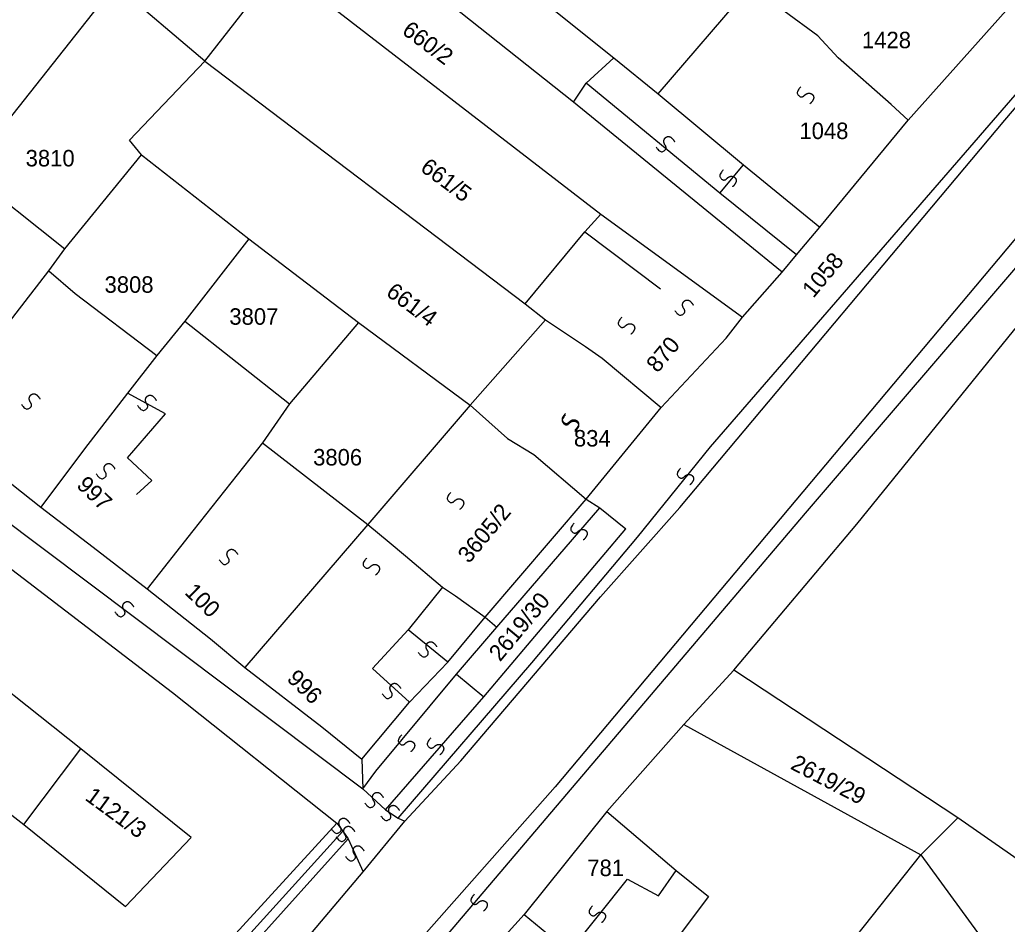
# Model space of a CAD drawing. Extents: x -581999 to -572728, y -1219553 to -1212032.
# Drawn here: x -577228 to -577108.1, y -1215298.5 to -1215188.7 of the extents above; entities that cross this region are included whole.
import ezdxf

# ---------------------------------------------------------------- set-up
doc = ezdxf.new("R2010")
doc.units = 0
for name, color, linetype in [('Vrstva 1', 7, 'Continuous'), ('Vrstva 2', 7, 'Continuous'), ('Vrstva 4', 7, 'Continuous'), ('Vrstva 6', 7, 'Continuous')]:
    doc.layers.add(name, color=color, linetype=linetype)

msp = doc.modelspace()

# ---------------------------------------------------------------- linework, layer by layer
at = {"layer": 'Vrstva 1'}
for p, q in [((-577108.375, -1215200.928), (-577078.069, -1215165.236)), ((-577147.827, -1215247.946), (-577108.375, -1215200.928)), ((-577133.659, -1215217.259), (-577130.847, -1215213.914)), ((-577135.394, -1215219.353), (-577133.659, -1215217.259)), ((-577171.444, -1215261.262), (-577159.184, -1215246.912)), ((-577159.184, -1215246.912), (-577157.533, -1215247.96)), ((-577157.533, -1215247.96), (-577154.401, -1215250.511)), ((-577157.469, -1215258.773), (-577147.827, -1215247.946)), ((-577171.626, -1215270.919), (-577154.401, -1215250.511)), ((-577174.413, -1215278.691), (-577157.469, -1215258.773)), ((-577171.444, -1215261.262), (-577170.06, -1215262.481)), ((-577174.954, -1215268.172), (-577170.06, -1215262.481)), ((-577174.954, -1215268.172), (-577171.626, -1215270.919)), ((-577129.473, -1215303.844), (-577118.578, -1215290.084)), ((-577217.998, -1215329.617), (-577186.261, -1215292.176))]:
    msp.add_line(p, q, dxfattribs=at)
for points in [[(-577068.022, -1215163.106), (-577076.012, -1215171.394), (-577092.817, -1215198.932), (-577107.282, -1215215.508), (-577162.965, -1215281.857), (-577201.26, -1215325.168), (-577221.372, -1215346.69), (-577272.951, -1215402.049), (-577277.91, -1215407.931), (-577301.723, -1215433.783), (-577314.534, -1215448.22), (-577343.272, -1215476.19), (-577359.94, -1215491.697), (-577381.842, -1215506.802), (-577421.443, -1215531.966), (-577436.182, -1215542.126), (-577449.269, -1215550.815), (-577464.697, -1215563.514), (-577494.524, -1215587.485), (-577505.622, -1215596.863)], [(-577185.738, -1215169.398), (-577155.834, -1215193.36)], [(-577160.721, -1215198.751), (-577190.451, -1215175.155)], [(-577205.47, -1215193.737), (-577196.448, -1215182.189)], [(-577196.448, -1215182.189), (-577157.432, -1215212.323)], [(-577234.283, -1215207.14), (-577216.388, -1215184.488)], [(-577205.47, -1215193.737), (-577216.388, -1215184.488)], [(-577150.438, -1215197.702), (-577139.236, -1215184.669)], [(-577131.067, -1215190.662), (-577139.236, -1215184.669)], [(-577120.088, -1215200.924), (-577108.226, -1215187.604)], [(-577128.594, -1215193.351), (-577131.067, -1215190.662)], [(-577213.172, -1215205.143), (-577214.626, -1215203.35), (-577205.47, -1215193.737)], [(-577205.47, -1215193.737), (-577166.603, -1215223.219)], [(-577160.721, -1215198.751), (-577159.192, -1215196.429), (-577155.834, -1215193.36)], [(-577155.834, -1215193.36), (-577150.438, -1215197.702)], [(-577122.184, -1215199.036), (-577128.594, -1215193.351)], [(-577150.438, -1215197.702), (-577140.115, -1215206.336)], [(-577141.262, -1215267.696), (-577126.334, -1215249.972), (-577109.753, -1215229.475), (-577083.861, -1215197.574)], [(-577144.536, -1215211.923), (-577160.721, -1215198.751)], [(-577120.088, -1215200.924), (-577122.184, -1215199.036)], [(-577130.847, -1215213.914), (-577120.088, -1215200.924)], [(-577222.485, -1215216.54), (-577213.172, -1215205.143)], [(-577213.172, -1215205.143), (-577200.13, -1215215.304)], [(-577234.283, -1215207.14), (-577222.485, -1215216.54)], [(-577140.115, -1215206.336), (-577130.847, -1215213.914)], [(-577159.361, -1215214.49), (-577157.432, -1215212.323)], [(-577157.432, -1215212.323), (-577140.223, -1215224.822)], [(-577135.394, -1215219.353), (-577144.536, -1215211.923)], [(-577166.603, -1215223.219), (-577159.361, -1215214.49)], [(-577200.13, -1215215.304), (-577207.914, -1215225.336)], [(-577200.13, -1215215.304), (-577186.851, -1215225.486)], [(-577224.409, -1215219.205), (-577222.485, -1215216.54)], [(-577238.546, -1215237.466), (-577224.409, -1215219.205)], [(-577224.409, -1215219.205), (-577221.221, -1215221.972)], [(-577140.223, -1215224.822), (-577135.394, -1215219.353)], [(-577221.221, -1215221.972), (-577211.314, -1215229.48)], [(-577166.603, -1215223.219), (-577164.123, -1215225.165)], [(-577207.914, -1215225.336), (-577211.314, -1215229.48)], [(-577207.914, -1215225.336), (-577195.231, -1215235.338)], [(-577186.851, -1215225.486), (-577195.231, -1215235.338)], [(-577186.851, -1215225.486), (-577173.281, -1215235.518)], [(-577164.123, -1215225.165), (-577173.281, -1215235.518)], [(-577164.123, -1215225.165), (-577159.29, -1215228.401)], [(-577142.221, -1215227.376), (-577140.223, -1215224.822)], [(-577150.088, -1215235.81), (-577142.221, -1215227.376)], [(-577159.29, -1215228.401), (-577157.264, -1215229.81)], [(-577211.314, -1215229.48), (-577214.863, -1215234.069)], [(-577157.264, -1215229.81), (-577150.088, -1215235.81)], [(-577214.863, -1215234.069), (-577220.113, -1215240.83), (-577225.399, -1215247.911)], [(-577195.231, -1215235.338), (-577198.488, -1215240.077)], [(-577173.281, -1215235.518), (-577185.691, -1215250.014)], [(-577173.281, -1215235.518), (-577168.763, -1215239.556)], [(-577159.184, -1215246.912), (-577150.088, -1215235.81)], [(-577168.763, -1215239.556), (-577165.551, -1215241.504)], [(-577248.988, -1215240.115), (-577209.412, -1215270.412), (-577189.463, -1215286.257)], [(-577198.488, -1215240.077), (-577206.934, -1215250.779)], [(-577198.488, -1215240.077), (-577185.691, -1215250.014)], [(-577165.551, -1215241.504), (-577159.184, -1215246.912)], [(-577228.905, -1215245.103), (-577225.399, -1215247.911)], [(-577225.399, -1215247.911), (-577219.046, -1215252.742)], [(-577185.691, -1215250.014), (-577200.649, -1215267.339)], [(-577185.691, -1215250.014), (-577183.111, -1215252.152)], [(-577206.934, -1215250.779), (-577212.473, -1215257.796)], [(-577219.046, -1215252.742), (-577212.473, -1215257.796)], [(-577183.111, -1215252.152), (-577181.149, -1215253.796)], [(-577181.149, -1215253.796), (-577176.621, -1215257.59)], [(-577212.473, -1215257.796), (-577204.809, -1215263.86)], [(-577176.621, -1215257.59), (-577175.048, -1215258.666)], [(-577175.048, -1215258.666), (-577171.444, -1215261.262)], [(-577175.991, -1215266.701), (-577171.444, -1215261.262)], [(-577204.809, -1215263.86), (-577200.649, -1215267.339)], [(-577220.526, -1215277.215), (-577236.987, -1215264.196)], [(-577200.649, -1215267.339), (-577191.287, -1215274.569)], [(-577180.645, -1215271.583), (-577175.991, -1215266.701)], [(-577141.262, -1215267.696), (-577147.321, -1215274.282)], [(-577114.068, -1215285.599), (-577141.262, -1215267.696)], [(-577186.41, -1215278.465), (-577180.645, -1215271.583)], [(-577244.216, -1215273.426), (-577227.468, -1215286.396)], [(-577191.287, -1215274.569), (-577186.41, -1215278.465)], [(-577147.321, -1215274.282), (-577156.671, -1215284.855)], [(-577147.321, -1215274.282), (-577118.578, -1215290.084)], [(-577227.468, -1215286.396), (-577220.526, -1215277.215)], [(-577215.107, -1215296.363), (-577207.151, -1215287.993), (-577220.526, -1215277.215)], [(-577186.261, -1215292.176), (-577181.218, -1215286.028), (-577174.413, -1215278.691)], [(-577156.671, -1215284.855), (-577166.722, -1215297.339)], [(-577156.671, -1215284.855), (-577148.284, -1215292.019)], [(-577227.468, -1215286.396), (-577215.107, -1215296.363)], [(-577189.463, -1215286.257), (-577209.205, -1215307.84)], [(-577118.578, -1215290.084), (-577114.068, -1215285.599)], [(-577081.938, -1215308.045), (-577088.871, -1215303.041), (-577093.984, -1215299.622), (-577114.068, -1215285.599)], [(-577118.578, -1215290.084), (-577098.683, -1215317.344)], [(-577148.284, -1215292.019), (-577144.353, -1215295.172), (-577153.716, -1215307.66)], [(-577166.722, -1215297.339), (-577176.589, -1215308.258)], [(-577166.722, -1215297.339), (-577161.237, -1215301.876)]]:
    msp.add_lwpolyline(points, dxfattribs=at)
at = {"layer": 'Vrstva 4'}
for p, q in [((-577142.974, -1215209.768), (-577159.192, -1215196.429)), ((-577132.562, -1215248.619), (-577090.817, -1215199.868)), ((-577133.659, -1215217.259), (-577142.974, -1215209.768)), ((-577249.841, -1215234.342), (-577186.307, -1215282.104)), ((-577210.283, -1215236.57), (-577214.863, -1215234.069)), ((-577214.862, -1215241.898), (-577210.283, -1215236.57)), ((-577211.931, -1215244.652), (-577214.862, -1215241.898)), ((-577213.788, -1215246.361), (-577211.931, -1215244.652)), ((-577170.06, -1215262.481), (-577157.533, -1215247.96)), ((-577182.387, -1215307.256), (-577132.562, -1215248.619)), ((-577175.991, -1215266.701), (-577180.816, -1215262.79)), ((-577184.741, -1215279.945), (-577174.954, -1215268.172)), ((-577183.567, -1215284.655), (-577171.626, -1215270.919)), ((-577186.41, -1215278.465), (-577186.307, -1215282.104)), ((-577186.307, -1215282.104), (-577184.741, -1215279.945)), ((-577186.307, -1215282.104), (-577183.567, -1215284.655)), ((-577183.567, -1215284.655), (-577182.001, -1215285.636)), ((-577189.463, -1215286.257), (-577188.743, -1215287.242)), ((-577182.001, -1215285.636), (-577181.218, -1215286.028)), ((-577234.361, -1215337.594), (-577188.743, -1215287.242)), ((-577188.743, -1215287.242), (-577188.079, -1215288.153)), ((-577233.254, -1215338.26), (-577188.079, -1215288.153)), ((-577188.079, -1215288.153), (-577186.261, -1215292.176))]:
    msp.add_line(p, q, dxfattribs=at)
for points in [[(-577144.108, -1215240.556), (-577100.564, -1215190.327), (-577076.885, -1215162.334)], [(-577142.974, -1215209.768), (-577140.115, -1215206.336)], [(-577159.361, -1215214.49), (-577150.171, -1215221.378)], [(-577152.982, -1215251.547), (-577144.108, -1215240.556)], [(-577165.808, -1215266.787), (-577152.982, -1215251.547)], [(-577176.621, -1215257.59), (-577180.816, -1215262.79), (-577185.154, -1215267.469)], [(-577180.645, -1215271.583), (-577185.154, -1215267.469)], [(-577182.001, -1215285.636), (-577165.808, -1215266.787)], [(-577161.237, -1215301.876), (-577154.18, -1215293.038), (-577150.431, -1215295.077), (-577148.284, -1215292.019)]]:
    msp.add_lwpolyline(points, dxfattribs=at)
at = {"layer": 'Vrstva 6'}
for points in [[(-577133.147, -1215196.876), (-577133.734, -1215197.498), (-577133.279, -1215198.107), (-577132.873, -1215198.095), (-577132.587, -1215197.79), (-577132.281, -1215197.636), (-577131.981, -1215197.652), (-577131.774, -1215197.754), (-577131.598, -1215197.957), (-577131.553, -1215198.321), (-577131.888, -1215198.833), (-577132.046, -1215198.925)], [(-577150.718, -1215204.172), (-577150.238, -1215204.879), (-577149.544, -1215204.568), (-577149.467, -1215204.168), (-577149.703, -1215203.823), (-577149.788, -1215203.491), (-577149.706, -1215203.201), (-577149.562, -1215203.021), (-577149.326, -1215202.893), (-577148.961, -1215202.929), (-577148.534, -1215203.368), (-577148.479, -1215203.541)], [(-577142.554, -1215206.961), (-577143.141, -1215207.583), (-577142.686, -1215208.192), (-577142.28, -1215208.18), (-577141.994, -1215207.875), (-577141.688, -1215207.721), (-577141.388, -1215207.737), (-577141.181, -1215207.839), (-577141.005, -1215208.042), (-577140.96, -1215208.406), (-577141.295, -1215208.918), (-577141.453, -1215209.01)], [(-577148.447, -1215224.017), (-577147.967, -1215224.724), (-577147.273, -1215224.413), (-577147.196, -1215224.013), (-577147.432, -1215223.668), (-577147.517, -1215223.336), (-577147.435, -1215223.046), (-577147.291, -1215222.866), (-577147.055, -1215222.738), (-577146.69, -1215222.774), (-577146.263, -1215223.213), (-577146.208, -1215223.386)], [(-577154.879, -1215224.855), (-577155.466, -1215225.477), (-577155.011, -1215226.086), (-577154.605, -1215226.074), (-577154.319, -1215225.769), (-577154.013, -1215225.615), (-577153.713, -1215225.631), (-577153.506, -1215225.733), (-577153.33, -1215225.936), (-577153.285, -1215226.3), (-577153.62, -1215226.812), (-577153.778, -1215226.904)], [(-577227.753, -1215235.404), (-577227.273, -1215236.111), (-577226.579, -1215235.8), (-577226.502, -1215235.4), (-577226.738, -1215235.055), (-577226.823, -1215234.723), (-577226.741, -1215234.433), (-577226.597, -1215234.253), (-577226.361, -1215234.125), (-577225.996, -1215234.161), (-577225.569, -1215234.6), (-577225.514, -1215234.773)], [(-577213.644, -1215235.568), (-577213.164, -1215236.275), (-577212.47, -1215235.964), (-577212.393, -1215235.564), (-577212.629, -1215235.219), (-577212.714, -1215234.887), (-577212.632, -1215234.597), (-577212.488, -1215234.417), (-577212.252, -1215234.289), (-577211.887, -1215234.325), (-577211.46, -1215234.764), (-577211.405, -1215234.937)], [(-577161.693, -1215236.514), (-577162.28, -1215237.136), (-577161.825, -1215237.745), (-577161.419, -1215237.733), (-577161.133, -1215237.428), (-577160.827, -1215237.274), (-577160.527, -1215237.29), (-577160.32, -1215237.392), (-577160.144, -1215237.595), (-577160.099, -1215237.959), (-577160.434, -1215238.471), (-577160.592, -1215238.563)], [(-577161.693, -1215236.677), (-577162.28, -1215237.299), (-577161.825, -1215237.908), (-577161.419, -1215237.896), (-577161.133, -1215237.591), (-577160.827, -1215237.437), (-577160.527, -1215237.453), (-577160.32, -1215237.555), (-577160.144, -1215237.758), (-577160.099, -1215238.122), (-577160.434, -1215238.634), (-577160.592, -1215238.726)], [(-577218.671, -1215243.863), (-577218.191, -1215244.57), (-577217.497, -1215244.259), (-577217.42, -1215243.859), (-577217.656, -1215243.514), (-577217.741, -1215243.182), (-577217.659, -1215242.892), (-577217.515, -1215242.712), (-577217.279, -1215242.584), (-577216.914, -1215242.62), (-577216.487, -1215243.059), (-577216.432, -1215243.232)], [(-577147.726, -1215243.151), (-577148.313, -1215243.773), (-577147.858, -1215244.382), (-577147.452, -1215244.37), (-577147.166, -1215244.065), (-577146.86, -1215243.911), (-577146.56, -1215243.927), (-577146.353, -1215244.029), (-577146.177, -1215244.232), (-577146.132, -1215244.596), (-577146.467, -1215245.108), (-577146.625, -1215245.2)], [(-577175.64, -1215246.111), (-577176.227, -1215246.733), (-577175.772, -1215247.342), (-577175.366, -1215247.33), (-577175.08, -1215247.025), (-577174.774, -1215246.871), (-577174.474, -1215246.887), (-577174.267, -1215246.989), (-577174.091, -1215247.192), (-577174.046, -1215247.556), (-577174.381, -1215248.068), (-577174.539, -1215248.16)], [(-577160.645, -1215249.823), (-577161.232, -1215250.445), (-577160.777, -1215251.054), (-577160.371, -1215251.042), (-577160.085, -1215250.737), (-577159.779, -1215250.583), (-577159.479, -1215250.599), (-577159.272, -1215250.701), (-577159.096, -1215250.904), (-577159.051, -1215251.268), (-577159.386, -1215251.78), (-577159.544, -1215251.872)], [(-577203.751, -1215254.274), (-577203.271, -1215254.981), (-577202.577, -1215254.67), (-577202.5, -1215254.27), (-577202.736, -1215253.925), (-577202.821, -1215253.593), (-577202.739, -1215253.303), (-577202.595, -1215253.123), (-577202.359, -1215252.995), (-577201.994, -1215253.031), (-577201.567, -1215253.47), (-577201.512, -1215253.643)], [(-577185.857, -1215254.082), (-577186.444, -1215254.704), (-577185.989, -1215255.313), (-577185.583, -1215255.301), (-577185.297, -1215254.996), (-577184.991, -1215254.842), (-577184.691, -1215254.858), (-577184.484, -1215254.96), (-577184.308, -1215255.163), (-577184.263, -1215255.527), (-577184.598, -1215256.039), (-577184.756, -1215256.131)], [(-577216.401, -1215260.618), (-577215.921, -1215261.325), (-577215.227, -1215261.014), (-577215.15, -1215260.614), (-577215.386, -1215260.269), (-577215.471, -1215259.937), (-577215.389, -1215259.647), (-577215.245, -1215259.467), (-577215.009, -1215259.339), (-577214.644, -1215259.375), (-577214.217, -1215259.814), (-577214.162, -1215259.987)], [(-577179.586, -1215265.498), (-577179.106, -1215266.205), (-577178.412, -1215265.894), (-577178.335, -1215265.494), (-577178.571, -1215265.149), (-577178.656, -1215264.817), (-577178.574, -1215264.527), (-577178.43, -1215264.347), (-577178.194, -1215264.219), (-577177.829, -1215264.255), (-577177.402, -1215264.694), (-577177.347, -1215264.867)], [(-577183.965, -1215270.541), (-577183.485, -1215271.248), (-577182.791, -1215270.937), (-577182.714, -1215270.537), (-577182.95, -1215270.192), (-577183.035, -1215269.86), (-577182.953, -1215269.57), (-577182.809, -1215269.39), (-577182.573, -1215269.262), (-577182.208, -1215269.298), (-577181.781, -1215269.737), (-577181.726, -1215269.91)], [(-577181.589, -1215275.529), (-577182.176, -1215276.151), (-577181.721, -1215276.76), (-577181.315, -1215276.748), (-577181.029, -1215276.443), (-577180.723, -1215276.289), (-577180.423, -1215276.305), (-577180.216, -1215276.407), (-577180.04, -1215276.61), (-577179.995, -1215276.974), (-577180.33, -1215277.486), (-577180.488, -1215277.578)], [(-577178.066, -1215275.921), (-577178.653, -1215276.543), (-577178.198, -1215277.152), (-577177.792, -1215277.14), (-577177.506, -1215276.835), (-577177.2, -1215276.681), (-577176.9, -1215276.697), (-577176.693, -1215276.799), (-577176.517, -1215277.002), (-577176.472, -1215277.366), (-577176.807, -1215277.878), (-577176.965, -1215277.97)], [(-577186.081, -1215283.782), (-577185.601, -1215284.489), (-577184.907, -1215284.178), (-577184.83, -1215283.778), (-577185.066, -1215283.433), (-577185.151, -1215283.101), (-577185.069, -1215282.811), (-577184.925, -1215282.631), (-577184.689, -1215282.503), (-577184.324, -1215282.539), (-577183.897, -1215282.978), (-577183.842, -1215283.151)], [(-577184.123, -1215285.352), (-577183.643, -1215286.059), (-577182.949, -1215285.748), (-577182.872, -1215285.348), (-577183.108, -1215285.003), (-577183.193, -1215284.671), (-577183.111, -1215284.381), (-577182.967, -1215284.201), (-577182.731, -1215284.073), (-577182.366, -1215284.109), (-577181.939, -1215284.548), (-577181.884, -1215284.721)], [(-577190.158, -1215286.911), (-577189.678, -1215287.618), (-577188.984, -1215287.307), (-577188.907, -1215286.907), (-577189.143, -1215286.562), (-577189.228, -1215286.23), (-577189.146, -1215285.94), (-577189.002, -1215285.76), (-577188.766, -1215285.632), (-577188.401, -1215285.668), (-577187.974, -1215286.107), (-577187.919, -1215286.28)], [(-577189.569, -1215287.895), (-577189.089, -1215288.602), (-577188.395, -1215288.291), (-577188.318, -1215287.891), (-577188.554, -1215287.546), (-577188.639, -1215287.214), (-577188.557, -1215286.924), (-577188.413, -1215286.744), (-577188.177, -1215286.616), (-577187.812, -1215286.652), (-577187.385, -1215287.091), (-577187.33, -1215287.264)], [(-577188.43, -1215290.258), (-577187.95, -1215290.965), (-577187.256, -1215290.654), (-577187.179, -1215290.254), (-577187.415, -1215289.909), (-577187.5, -1215289.577), (-577187.418, -1215289.287), (-577187.274, -1215289.107), (-577187.038, -1215288.979), (-577186.673, -1215289.015), (-577186.246, -1215289.454), (-577186.191, -1215289.627)], [(-577172.774, -1215294.886), (-577173.361, -1215295.508), (-577172.906, -1215296.117), (-577172.5, -1215296.105), (-577172.214, -1215295.8), (-577171.908, -1215295.646), (-577171.608, -1215295.662), (-577171.401, -1215295.764), (-577171.225, -1215295.967), (-577171.18, -1215296.331), (-577171.515, -1215296.843), (-577171.673, -1215296.935)], [(-577158.419, -1215296.275), (-577159.006, -1215296.897), (-577158.551, -1215297.506), (-577158.145, -1215297.494), (-577157.859, -1215297.189), (-577157.553, -1215297.035), (-577157.253, -1215297.051), (-577157.046, -1215297.153), (-577156.87, -1215297.356), (-577156.825, -1215297.72), (-577157.16, -1215298.232), (-577157.318, -1215298.324)]]:
    msp.add_open_spline(points, degree=2, dxfattribs=at)

# ---------------------------------------------------------------- texts
at = {"layer": 'Vrstva 2'}
for s, rotation, p in [('660/2', 323.42936, (-577181.682, -1215190.34)), ('661/5', 323.42936, (-577179.456, -1215206.982)), ('1058', 50.27529, (-577131.615, -1215222.614)), ('661/4', 323.42936, (-577183.617, -1215222.105)), ('870', 50.27529, (-577150.533, -1215231.69)), ('997', 315.86443, (-577221.17, -1215245.361)), ('3605/2', 50.27529, (-577173.42, -1215254.827)), ('100', 315.86443, (-577208.044, -1215258.35)), ('2619/30', 50.27529, (-577169.646, -1215266.738)), ('996', 315.86443, (-577195.643, -1215268.846)), ('2619/29', 332.4627, (-577134.518, -1215279.606)), ('1121/3', 323.7862, (-577220.144, -1215283.361))]:
    msp.add_text(s, height=2, rotation=rotation, dxfattribs=at).set_placement(p)
for s, p in [('1428', (-577125.715, -1215192.188)), ('1048', (-577133.311, -1215203.211)), ('3810', (-577227.242, -1215206.534)), ('3808', (-577217.662, -1215221.871)), ('3807', (-577202.514, -1215225.753)), ('834', (-577160.686, -1215240.532)), ('3806', (-577192.344, -1215242.833)), ('781', (-577159.059, -1215292.68))]:
    msp.add_text(s, height=2, dxfattribs=at).set_placement(p)

doc.saveas('drawing.dxf')
